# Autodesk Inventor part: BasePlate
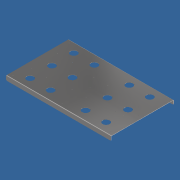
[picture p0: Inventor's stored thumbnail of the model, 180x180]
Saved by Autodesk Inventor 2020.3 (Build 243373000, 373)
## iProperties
Created: 2020-09
Part Number: BasePlate
Material: Stainless Steel
Document SubType Name: Sheet Metal
Designer: biggshj
Manufacturer: Standard
Standards Organization: Custom
Mass: 36081.5 g
Surface Area: 18413.5 cm^2
Volume: 4510.18 cm^3
Density: 8 g/cm^3
Appearance: Semi-Polished
Flat Pattern Width: 80.2619 cm
Flat Pattern Length: 120 cm
Flat Pattern Area: 9631.43 cm^2
Sheet Metal Rule: Default
Sheet Metal Width: 802.619 mm
Sheet Metal Length: 1200.000 mm
Sheet Metal Area: 963143.361 mm^2
Company: NIWA Instrument Systems
Author: biggshj
Revision Number: 1
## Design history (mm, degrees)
sketch "Sketch1"
  geometry: L1 (-600, -350)-(600, -350); L2 (600, -350)-(600, 350); L3 (600, 350)-(-600, 350); L4 (-600, 350)-(-600, -350); 3 further points
  constraints: 8 end point, 2 midpoint, 2 parallel, 1 horizontal, 1 horizontal alignment, 1 perpendicular, 1 vertical alignment
  dimensions: "d0" = 1200 distance of L2.end L3.end; "d1" = 700 distance of L1.end L2.end
extrude "Extrusion1" new body sketch "Sketch1" distance "d2" = 5 (= Thickness); taper "d3" = 0 deg
node "Flange1"
sketch "Sketch5"
  geometry: L1 (-430, 0)-(-600, 0); L2 (840, 0)-(-840, 0) reference; L3 (-385, -87.486)-(-475, -87.486); L4 (-475, -87.486)-(-475, 87.486); L5 (-475, 87.486)-(-385, 87.486); L6 (-385, 87.486)-(-385, -87.486); L7 (-385, -87.486)-(-475, 87.486); L8 (-475, -87.486)-(-385, 87.486); L9 (-600, -350)-(-600, 350) reference; 1 further point
  constraints: 14 end point, 3 midpoint, 2 parallel, 1 collinear, 1 horizontal, 1 perpendicular
  dimensions: "d84" = 170 distance of L1.start L1.end; "d113" = 174.972 distance of L5.end L3.start; "d114" = 90 distance of L4.end L5.end
hole "Hole1" sketch "Sketch5" at (-475, 87.486), (-475, -87.486), (-385, -87.486), (-385, 87.486) diameter "d87" = 8.5; stored, may be unused: countersink angle "d91" = 90 deg, drill point angle "d93" = 118 deg; dims "d88" = 6, "d89" = 4, "d90" = 2, "d92" = 5 (= Thickness)
sketch "Sketch8"
  geometry: C1 r 4.025 at (0, 0); 1 further point
  constraints: 1 centre point, 1 coincident
  dimensions: "d43" = 8.05 diameter of C1
extrude "Extrusion7" cut sketch "Sketch8" distance "d44" = 10; taper "d45" = 0 deg
pattern_linear "Rectangular Pattern1" dims "d48" = 560, "d51" = 320
sketch "Sketch10"
  geometry: L1 (520, -150)-(350, -150); L2 (350, -150)-(350, 150); L3 (350, 150)-(520, 150); L4 (520, 150)-(520, -150); L5 (520, -150)-(350, 150); L6 (350, -150)-(520, 150); C1 r 4.025 at (0, 0) reference; 3 further points
  constraints: 12 end point, 3 midpoint, 2 parallel, 1 horizontal, 1 horizontal alignment, 1 perpendicular
  dimensions: "d94" = 170 distance of L2.end L3.end; "d95" = 300 distance of L1.end L2.end; "d96" = 350 distance from line of point (0, 0) L2
sketch "Sketch11"
  geometry: L1 (0, 0)-(200, 0); C1 r 4.025 at (0, 0) reference; C2 r 40 at (200, 0); 1 further point
  constraints: 2 end point, 1 centre point, 1 coincident, 1 horizontal
  dimensions: "d71" = 80 diameter of C2; "d72" = 200 distance of L1.start L1.end
extrude "Extrusion10" cut sketch "Sketch11" distance "d73" = 10; taper "d74" = 0 deg
pattern_linear "Rectangular Pattern3" dims "d77" = 235, "d80" = 250
mirror "Mirror6"
fillet "Fillet6" dims "d24" = 10
hole "Hole2" sketch "Sketch10" diameter "d97" = 8.5; stored, may be unused: countersink angle "d101" = 90 deg, drill point angle "d103" = 118 deg; dims "d98" = 6, "d99" = 4, "d100" = 2, "d102" = 5 (= Thickness)
sketch "Sketch9"
  geometry: L1 (0, 0)-(0, 125); L2 (80, -125)-(-80, -125); L3 (-80, -125)-(-80, 125); L4 (-80, 125)-(80, 125); L5 (80, 125)-(80, -125); L6 (80, -125)-(-80, 125); L7 (-80, -125)-(80, 125); C1 r 4.025 at (0, 0) reference; 1 further point
  constraints: 14 end point, 2 midpoint, 2 parallel, 1 horizontal, 1 perpendicular, 1 vertical
  dimensions: "d104" = 160 distance of L3.end L4.end; "d105" = 250 distance of L4.end L2.start
hole "Hole3" sketch "Sketch9" diameter "d106" = 8.5; stored, may be unused: countersink angle "d110" = 90 deg, drill point angle "d112" = 118 deg; dims "d107" = 6, "d108" = 4, "d109" = 2, "d111" = 5 (= Thickness)
body "Solid1"
sketch "Sketch4"
  geometry: L1 through (600, 0) direction (-1, 0); L2 through (0, -20) direction (0, -1); L3 (0, -40)-(1200, -40); L4 (1200, -40)-(1200, 0)
  constraints: 6 end point, 1 horizontal, 1 perpendicular, 1 vertical
face "Plate1" dims "d10" = 5 (= Thickness), "d11" = 5 (= BendReliefWidth), "d12" = 2.5 (= BendReliefDepth), "d13" = 10 (= MinimumRemnant), "d14" = 5 (= TransitionRadius), "d15" = 50, "d16" = 90 deg, "d17" = 5 (= BendRadius), "d18" = 20 (= CornerReliefSize), "d19" = 5 (= GapSize), "d20" = 5 (= JacobiRadiusSize), "SeamGap" = 0.01
bend "Bend1" dims "d10" = 5 (= Thickness), "d11" = 5 (= BendReliefWidth), "d12" = 2.5 (= BendReliefDepth), "d13" = 10 (= MinimumRemnant), "d14" = 5 (= TransitionRadius), "d15" = 50, "d16" = 90 deg, "d17" = 5 (= BendRadius), "SeamGap" = 0.01
feature "Corner1" dims "d15" = 50, "d16" = 90 deg, "d18" = 20 (= CornerReliefSize), "d19" = 5 (= GapSize), "d20" = 5 (= JacobiRadiusSize)
feature "Definition1"
feature "耀쁁"
other parameters: "Thickness" = 5, "KFactor" = 4.4, "BendRadius" = 5 (= Thickness), "BendReliefWidth" = 5 (= Thickness), "BendReliefDepth" = 2.5 (= 0.5 x Thickness), "TransitionRadius" = 5 (= BendRadius), "JacobiRadiusSize" = 5 (= Thickness), "GapSize" = 5 (= Thickness), "BendRadius" = 5, "BendReliefDepth" = 2.5, "BendReliefWidth" = 5, "GapSize" = 5, "JacobiRadiusSize" = 5, "Thickness" = 5, "TransitionRadius" = 5
